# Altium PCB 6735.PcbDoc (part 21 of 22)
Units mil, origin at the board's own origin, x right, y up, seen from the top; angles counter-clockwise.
Board outline 2641.73 x 5165.35 mil, 6 copper layers (Top, Inner Layer 2, Inner Layer 3, Inner Layer 4, Inner Layer 5, Bottom), stack 35.7 mil thick; 1011 components, 790 nets, 4118 pads, 9325 vias.
Unrouted connection lines stored in the file: 4610.
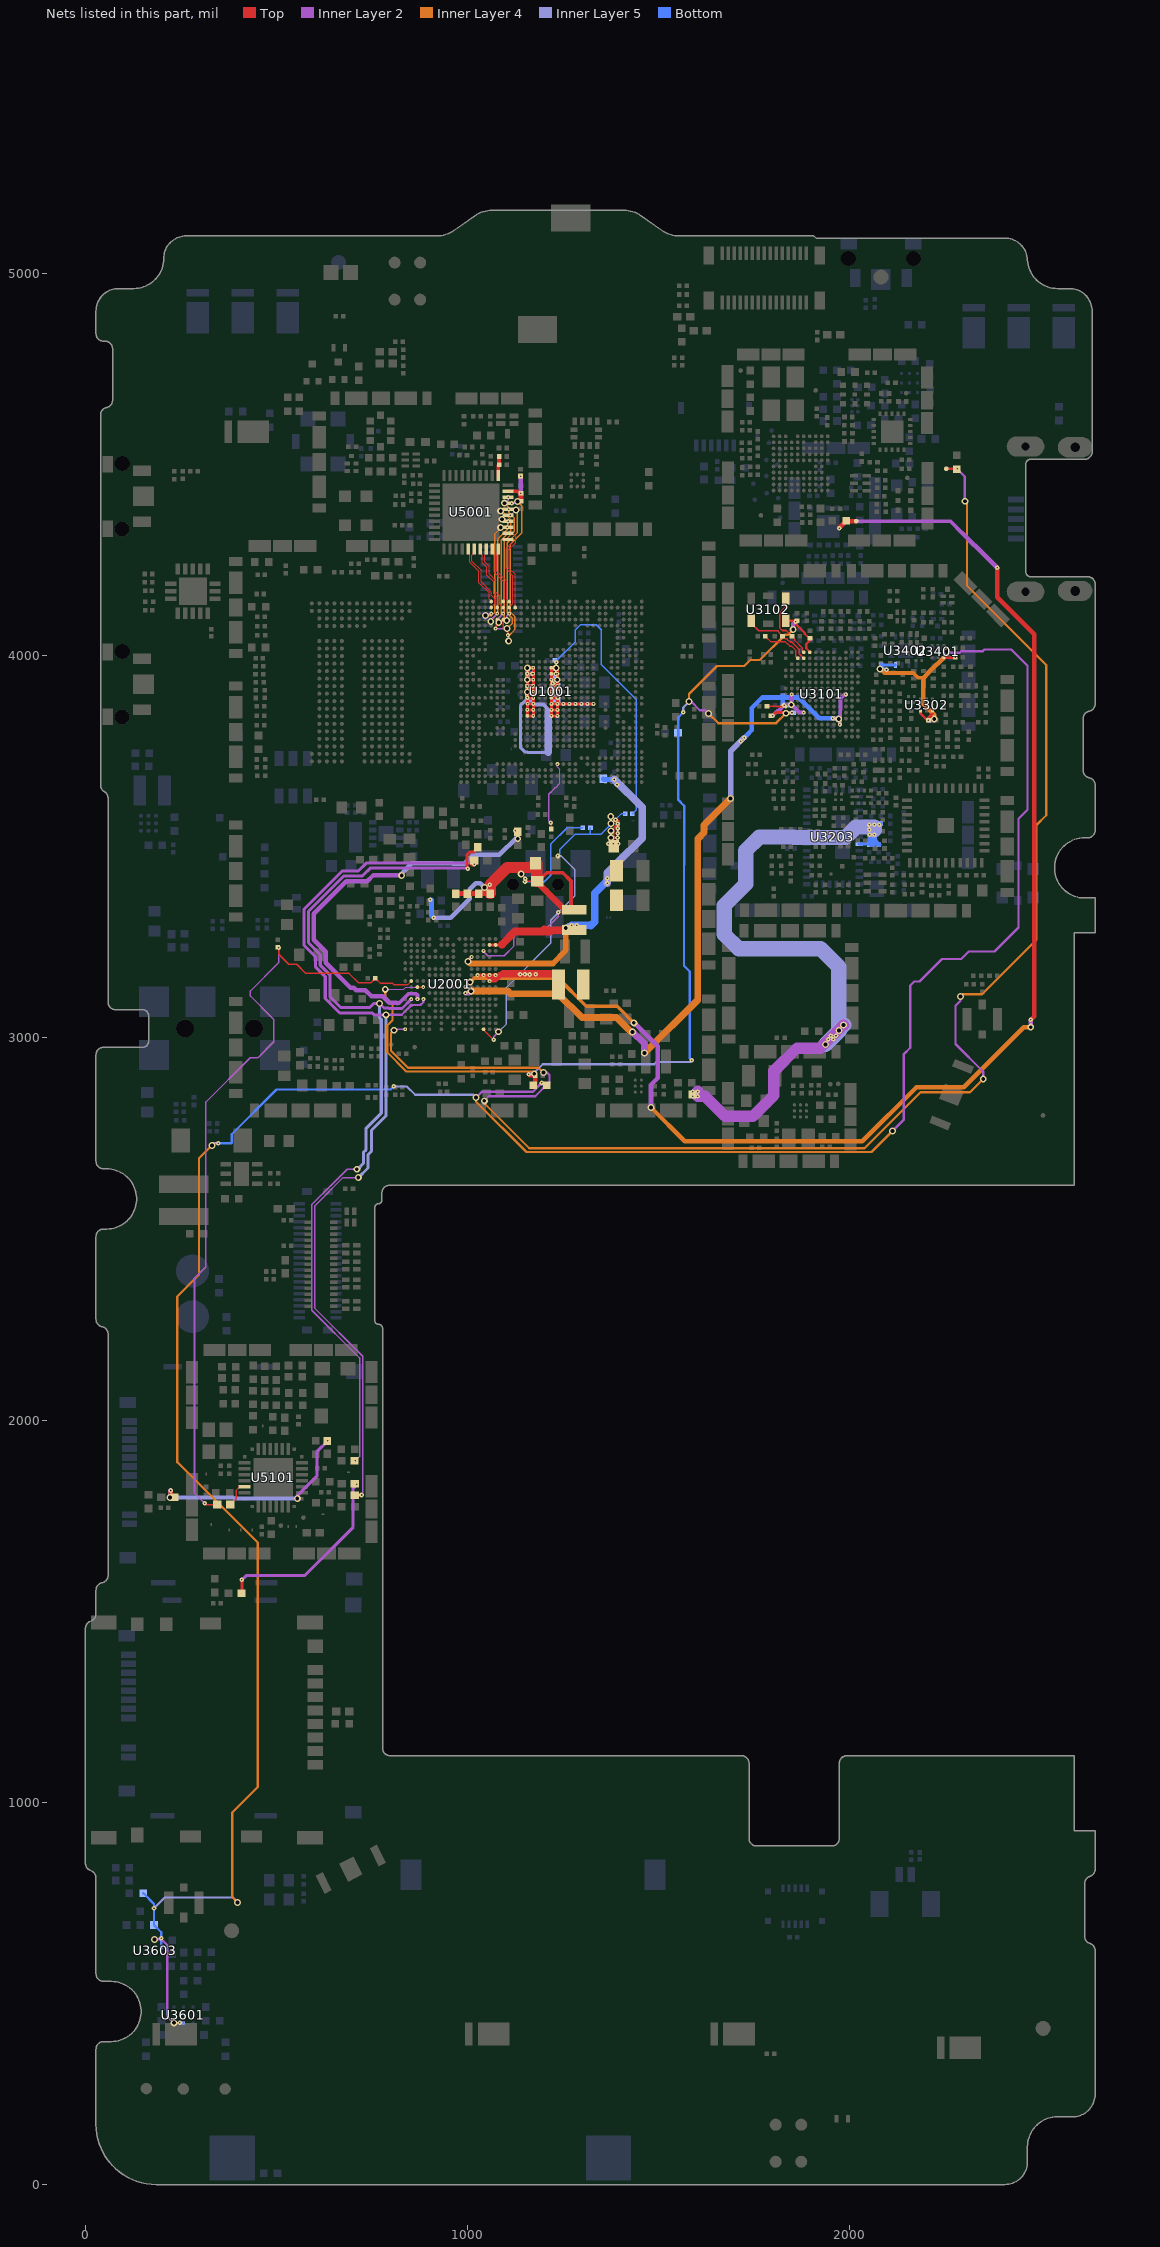
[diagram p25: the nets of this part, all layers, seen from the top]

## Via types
v1: diameter 12, hole 4, Top to Inner Layer 2, 3329 vias
v2: diameter 12, hole 4, Inner Layer 5 to Bottom, 3071 vias
v3: diameter 18, hole 10, Inner Layer 2 to Inner Layer 5, 1928 vias
v4: diameter 10, hole 4, Top to Inner Layer 2, 525 vias
v5: diameter 20, hole 12, Top to Bottom, 472 vias

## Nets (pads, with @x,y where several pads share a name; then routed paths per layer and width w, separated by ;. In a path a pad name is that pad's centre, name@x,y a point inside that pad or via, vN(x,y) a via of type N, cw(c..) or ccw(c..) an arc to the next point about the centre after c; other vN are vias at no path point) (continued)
VPA_VCC2: C3205.1 C3233.1 C3242.1 C3243.1 R3234.1 U3203.28 U3203.30 | length 2323.3
  Top w4: v1(1589.27,2859.22) 1589.38,2859.11 1586.84,2856.56 1587.31,2856.09 R3234.1@1587.31,2852.09 ; v1(1602.31,2847.09) 1594.85,2848.41 1594.42,2847.98 1590.31,2852.09 R3234.1@1587.31,2852.09 ; v1(1602.31,2859.09) 1602.39,2859.81 1595.7,2860.47 1591.86,2856.63 R3234.1@1587.31,2852.09 ; v1(1950.15,3006.09) 1949.32,3005.25 1957.71,2996.86 v1(1956.88,2996.02)
  Inner Layer 2 w4: v1(1963.65,3006.09) v3@1963.65,3014.28
  Inner Layer 2 w30: v1(1602.31,2847.09) 1621.13,2847.09 1673.66,2794.56 1745.99,2794.56 1800.95,2849.52 1800.95,2912.49 1861.76,2973.3 1922.67,2973.3 1963.65,3014.28 1982.96,3033.59 v3(1983.65,3033.59) ; v1(1602.31,2859.09) v1@1602.31,2860.45
  Inner Layer 5 w12: 2063.65,3551.59 v2@2063.65,3557.34 ; v2@2050.59,3557.09 2051.09,3557.09 2051.09,3551.59 v2@2051.09,3545.03 ; v2@2050.59,3557.09 v2(2050.52,3557.09) 2050.52,3557.34 v2@2063.4,3557.34 ; v2@2050.59,3557.09 2050.59,3551.59 2050.59,3544.59 v2(2050.65,3544.59) ; v2(2050.65,3544.59) v2(2050.65,3544.59) ; v2(2050.65,3544.59) v2(2050.65,3544.59) ; v2(2050.65,3544.59) v2(2050.65,3544.59) ; v2(2050.65,3544.59) v2@2051.09,3544.23 ; v2(2050.65,3544.59) v2@2051.09,3544.59 ; v2(2050.65,3544.59) v2@2051.09,3545.03 ; v2@2051.09,3544.23 2051.09,3531.59 v2(2051.65,3531.59) 2051.65,3531.39 v2@2063.93,3531.39 ; v2@2051.09,3544.23 v2@2051.09,3544.59 ; v2@2051.09,3544.23 v2@2063.93,3531.39 ; v2@2051.09,3544.59 v2@2051.09,3545.03 ; v2@2051.09,3544.59 2063.65,3544.59 ; v2@2051.09,3545.03 2057.65,3551.59 v2@2063.4,3557.34 ; v2@2063.4,3557.34 v2@2063.65,3557.34 ; v2@2063.4,3557.34 v2(2063.65,3557.59) v2@2063.65,3557.51 ; 2063.65,3544.59 2063.74,3544.51 2063.82,3544.59 ; 2063.65,3544.59 2063.82,3544.59 ; v2@2063.65,3557.34 v2@2063.65,3557.51 ; v2@2063.65,3557.51 v2@2076.74,3557.51 ; 2063.82,3544.59 2063.93,3544.59 v2@2063.93,3531.39 ; 2063.82,3544.59 v2@2076.74,3557.51 ; v2@2063.93,3531.39 2063.93,3531.18 v2@2064.13,3531.18 ; v2@2063.93,3531.39 v2@2064.13,3531.18 ; v2@2063.93,3531.39 2064.21,3531.39 v2(2064.21,3531.18) ; v2@2064.13,3531.18 v2(2064.21,3531.18) v2(2064.21,3531.18) ; v2@2064.13,3531.18 v2(2064.21,3531.18) ; v2(2064.21,3531.18) 2076.82,3543.79 v2(2076.82,3557.43) ; v2@2076.74,3557.51 2076.82,3557.51 v2(2076.82,3557.43) ; v2@2076.74,3557.51 v2(2076.82,3557.43)
  Inner Layer 5 w30: v3(1971.15,3019.09) v3@1971.9,3018.34
  Inner Layer 5 w40: v3(1936.15,2982.59) v3@1971.9,3018.34 ; v3(1971.15,3019.09) v3@1971.15,3021.09 ; v3(1983.65,3033.59) v3@1971.15,3021.09 ; 2063.65,3544.59 2063.65,3551.59 2057.65,3551.59 2051.09,3551.59 2050.59,3551.59 2015.48,3551.59 1988.48,3524.59 1853.96,3524.59 1852.96,3525.59 1763.15,3525.59 1727.56,3490 1727.56,3402.73 1671.31,3346.48 1671.31,3271.15 1708.97,3233.5 1923.13,3233.5 1971.15,3185.48 v3@1971.15,3021.09
  Bottom w4: C3205.1@2050.65,3505.59 2051.65,3505.59 2053.94,3505.59 2061.65,3505.59 C3242.1@2075.65,3505.59 ; C3243.1@2055.65,3560.59 2055.65,3558.66 2055.65,3557.59 v2(2063.65,3557.59)
  Bottom w8: U3203.30@2024.55,3506.89 2050.65,3506.89 2051.28,3506.07 C3205.1@2051.65,3505.59 ; U3203.28@2024.55,3544.29 2047.72,3544.29 2049.34,3545.91 2050.52,3547.09 v2(2050.52,3557.09)
  Bottom w12: v2(2050.65,3544.59) v2@2051.09,3545.03 ; C3205.1@2053.94,3505.59 2051.65,3507.87 2051.65,3517.59 ; C3243.1@2055.65,3558.66 2050.52,3558.66 v2(2050.52,3557.09) C3243.1@2051.09,3557.09 ; 2061.65,3505.59 2064.65,3508.59 2064.65,3516.59 ; v2(2063.65,3557.59) 2063.65,3560.59 C3233.1@2080.65,3560.59 ; C3242.1@2076.65,3505.59 C3242.1@2075.65,3505.59 2064.65,3516.59 ; v2(2076.82,3557.43) 2076.17,3558.08 2064.65,3546.56 2064.65,3531.18 2064.65,3516.59 ; v2@2051.09,3545.03 2051.09,3531.59 v2(2051.65,3531.59) ; v2@2051.09,3545.03 C3243.1@2051.09,3557.09 ; v2@2051.09,3545.03 2051.15,3545.09 2060.65,3535.59 2060.65,3547.59 2051.15,3557.09 C3243.1@2051.09,3557.09 ; 2051.65,3517.59 2053.65,3517.59 2057.65,3513.59 2061.65,3513.59 2064.65,3516.59 ; 2051.65,3517.59 v2@2051.65,3529.59 ; v2@2051.65,3529.59 v2(2051.65,3531.59) ; v2@2051.65,3529.59 2050.65,3530.59 v2(2051.65,3531.59) ; v2@2051.65,3529.59 2064.65,3516.59
  other v1: 1589.31,2847.09 1943.15,2996.09
VPROC_PMIC_FB: R1036.1 SH1001.2 | length 551.6
  Bottom w4: SH1001.2@1328.31,4081.09 1336.31,4081.09 1349.31,4068.09 1349.31,3977.28 1441.31,3885.28 1441.31,3596.09 1431.31,3586.09 R1036.1@1430.31,3586.09
VPROC_PMIC_FB_6328: R1036.2 R2034.1 U2001.C16 | length 878.5
  Top w4: v1(1067.95,2994.83) 1054.12,3008.66 1053.63,3008.66 1040.57,3021.72 U2001.C16@1041.57,3022.72 ; U2001.C16@1041.57,3022.72 1041.67,3022.83 U2001.C16@1041.57,3022.72
  Inner Layer 2 w4: v1(1067.95,2994.83) 1067.95,3003.2 v3(1080.98,3016.23)
  Inner Layer 5 w4: v3(1080.98,3016.23) 1101.31,3036.56 1101.31,3132.09 1217.31,3248.09 1217.31,3308.09 1280.31,3371.09 1280.31,3440.4 1244.63,3476.09 1236.38,3476.09 v2(1236.3,3476.01)
  Bottom w4: v2(1236.3,3476.01) 1241.31,3481.02 1241.31,3493.47 1280.93,3533.09 1321.31,3533.09 ; R2034.1@1321.31,3550.09 1321.31,3533.09 ; R1036.2@1412.31,3586.09 1401.48,3586.09 1348.48,3533.09 1321.31,3533.09
VPROC_PMU: C10036.1 C10038.1 C10040.1 C10046.1 C10047.1 C10052.1 C10053.1 C10059.1 C10060.1 C10062.1 C10064.1 L2001.2 SH1001.1 U1001.AA14 U1001.AB14 U1001.AC14 U1001.M12 U1001.M13 U1001.M15 U1001.M16 U1001.M17 U1001.M18 U1001.M19 U1001.M20 U1001.N12 U1001.N13 U1001.N14 U1001.N15 U1001.N16 U1001.N17 U1001.N18 U1001.N19 U1001.N20 U1001.T12 U1001.T13 U1001.T14 U1001.T15 U1001.T16 U1001.T17 U1001.T18 U1001.T19 U1001.T20 U1001.U12 U1001.U13 U1001.U14 U1001.U15 U1001.U16 U1001.U17 U1001.U18 U1001.U19 U1001.U20 U1001.V14 U1001.W14 U1001.Y14 | length 2209.6
  Top w4: U1001.M16@1155.96,3905.49 v4(1155.96,3889.74) ; v4(1171.71,3889.74) v4(1155.96,3889.74) ; v1(1368.29,3507.98) 1374.89,3502.98 1376.9,3505.63 1377.21,3506.04 1378.85,3504.8 C10040.1@1381.9,3502.49 ; v1(1392.42,3560.25) 1392.2,3560.02 1382.36,3550.19 C10040.1@1382.36,3507.43 ; v1(1394.4,3507.85) 1390.08,3505.61 1389.31,3507.09 1387.96,3507.09 C10040.1@1382.36,3501.49 ; v4(1155.96,3889.74) 1155.96,3882.48 U1001.M15@1155.96,3889.74 ; C10040.1@1381.9,3502.49 1382.01,3501.45 1382.52,3496.58 1383.31,3496.58 1383.31,3500.54 C10040.1@1382.36,3501.49 ; C10040.1@1381.9,3502.49 v1(1381.31,3508.05) C10040.1@1382.36,3507.43 ; C10040.1@1381.9,3502.49 C10040.1@1382.36,3502.14 ; C10040.1@1382.36,3501.49 C10040.1@1382.36,3502.14 ; C10040.1@1382.36,3501.49 C10040.1@1382.36,3507.43 ; C10040.1@1382.36,3502.14 C10040.1@1382.36,3507.43
  Top w8: 1155.96,3882.48 v4@1155.96,3875.49 ; v4(1171.71,3858.25) v4(1155.96,3858.25) ; v4(1171.71,3873.99) v4@1157.45,3873.99 ; U1001.N15@1171.71,3889.74 1155.96,3889.74 U1001.M16@1155.96,3905.49 ; v4(1171.71,3905.49) U1001.M16@1155.96,3905.49 ; v4(1171.71,3921.24) v4(1155.96,3921.24) ; v4(1171.71,3936.99) U1001.M18@1155.96,3936.99 ; v4(1171.71,3952.73) v4(1155.96,3952.73) ; v4(1329.19,3873.99) v4(1266.2,3873.99) v4(1234.7,3873.99) ; v4(1155.96,3858.25) U1001.M12@1155.96,3842.5 v4(1171.71,3842.5) v4(1171.71,3968.48) ; v4(1155.96,3858.25) v4@1155.96,3875.49 ; v4@1155.96,3875.49 v4(1156.95,3874.49) ; v4@1155.96,3875.49 v4@1156.95,3874.49 ; U1001.M16@1155.96,3905.49 v4(1155.96,3921.24) ; v4(1155.96,3921.24) U1001.M18@1155.96,3936.99 ; U1001.M18@1155.96,3936.99 v4(1155.96,3952.73) ; U1001.M18@1155.96,3936.99 v4(1155.96,3952.73) ; U1001.M18@1155.96,3936.99 v4(1155.96,3952.73) ; v4(1155.96,3952.73) U1001.M20@1155.96,3968.48 ; v4(1155.96,3952.73) U1001.M20@1155.96,3968.48 ; v4(1155.96,3952.73) U1001.M20@1155.96,3968.48 ; U1001.M20@1155.96,3968.48 v4(1171.71,3968.48) ; U1001.M20@1155.96,3968.48 v4(1171.71,3968.48) ; v4(1156.95,3874.49) v4@1157.45,3873.99 ; v4@1156.95,3874.49 v4@1157.45,3873.99 ; v4(1218.95,3858.25) v4(1234.7,3858.25) ; v4(1218.95,3858.25) v4(1218.95,3873.99) ; v4(1218.95,3858.25) v4(1218.95,3842.5) v4(1234.7,3842.5) v4(1234.7,3858.25) ; v4(1218.95,3873.99) U1001.T15@1218.95,3889.74 ; v4(1218.95,3873.99) v4(1234.7,3873.99) ; U1001.T15@1218.95,3889.74 U1001.U15@1234.7,3889.74 ; U1001.T15@1218.95,3889.74 v4(1218.95,3905.49) ; v4(1218.95,3905.49) U1001.U16@1234.7,3905.49 ; v4(1218.95,3905.49) U1001.T17@1218.95,3921.24 ; U1001.T17@1218.95,3921.24 v4(1234.7,3921.24) ; U1001.T17@1218.95,3921.24 v4(1218.95,3936.99) ; v4(1218.95,3936.99) U1001.U18@1234.7,3936.99 ; v4(1218.95,3936.99) U1001.T19@1218.95,3952.73 ; v4(1218.95,3936.99) U1001.U18@1234.7,3936.99 ; U1001.T19@1218.95,3952.73 v4(1234.7,3952.73) ; U1001.T19@1218.95,3952.73 U1001.T20@1218.95,3968.48 ; U1001.T20@1218.95,3968.48 U1001.U20@1234.7,3968.48 ; U1001.T20@1218.95,3968.48 U1001.U20@1234.7,3968.48 ; v4(1234.7,3858.25) v4(1234.7,3873.99) ; v4(1234.7,3873.99) U1001.U15@1234.7,3889.74 ; v4(1234.7,3889.74) U1001.U16@1234.7,3905.49 ; U1001.U16@1234.7,3905.49 v4(1234.7,3921.24) ; v4(1234.7,3921.24) U1001.U18@1234.7,3936.99 ; v4(1234.7,3921.24) U1001.U18@1234.7,3936.99 ; U1001.U18@1234.7,3936.99 v4(1234.7,3952.73) ; U1001.U18@1234.7,3936.99 v4(1234.7,3952.73) ; v4(1234.7,3952.73) U1001.U20@1234.7,3968.48 ; v4(1234.7,3952.73) U1001.U20@1234.7,3968.48
  Top w12: v1(1386.78,3571.02) 1392.2,3565.6 1392.2,3560.02 v1(1392.2,3547.96)
  Inner Layer 2 w8: v4(1155.96,3889.74) v3(1156.08,3905.1) ; v4(1171.71,3873.99) v4(1171.71,3905.49) 1156.08,3905.49 v3(1156.08,3968.1) 1156.45,3968.48 v4(1171.71,3968.48) ; v4(1218.95,3905.49) v3@1234.08,3905.49 ; v4(1218.95,3936.99) v3@1234.08,3936.98 ; v3(1231.58,3968.11) 1234.08,3965.61 v3@1234.08,3936.98 ; v3(1234.39,3937.1) v3@1234.08,3936.98 ; v4(1329.19,3873.99) v4(1313.44,3873.99) v4(1234.7,3873.99) ; v4@1234.08,3873.99 v4(1234.7,3873.99) ; v4@1234.08,3873.99 v4(1234.7,3873.99) ; v4@1234.08,3873.99 v3(1234.08,3905.1) v3@1234.08,3905.49 ; v3@1234.08,3905.49 1234.08,3921.24 v3@1234.08,3936.98
  Inner Layer 5 w4: v3@1156.08,3966.62 v3(1156.08,3968.1)
  Inner Layer 5 w8: v2(1155.92,3889.98) 1157.45,3888.45 1137.95,3868.96 1137.95,3760.49 1150.95,3747.49 1156.64,3747.49 1157.03,3747.1 1210.56,3747.1 1210.95,3747.49
  Inner Layer 5 w10: v2(1155.95,3952.49) 1156.07,3966.6 v3(1156.08,3968.1) ; v2@1157.45,3888.45 1173.41,3872.49 1198.51,3872.49 1210.95,3860.04 1210.95,3853.44
  Inner Layer 5 w20: 1210.95,3747.49 1210.95,3853.44
  Bottom w4: v2(1231.38,3983.3) C10053.1@1228.31,3988.09 1233.31,3988.09 1281.31,4036.09 1281.31,4066.9 1295.5,4081.09 SH1001.1@1324.31,4081.09 ; C10060.1@1227.4,3951.6 v2(1230.31,3952.09) 1228.31,3951.09 C10060.1@1228.31,3946.09 C10060.1@1227.4,3951.6
  Bottom w12: v2(1155.95,3920.49) v2(1169.95,3920.49) ; C10064.1@1155.95,3946.49 v2(1155.95,3952.49) v2(1168.95,3952.49)
  other v1: 1392.04,3523.31 1392.29,3535.67
  other v2: 1236.45,3889.86 1221.75,3896.01 1223.09,3915.71 1222.31,3928.09
  other v3: 1375.31,3523.57 1375.31,3541.82 1375.31,3560.86 1374.19,3579.32 1156.02,3937.04
  other v4: 1250.45,3873.99 1281.94,3873.99 1297.69,3873.99
VPROC_SW: L2001.1 U2001.A7 U2001.B7 U2001.B8 U2001.C7 U2001.D7 | length 518
  Top w4: v4(1025.82,3164.45) v4(1041.57,3164.45)
  Top w8: v4(1025.82,3164.45) v4(1041.57,3164.45) 1048.15,3164.45 ; 1048.15,3164.45 v4(1057.32,3164.45) ; 1048.15,3164.45 1057.31,3155.29 ; v4(1057.32,3148.7) 1060.61,3152 1057.54,3155.06 ; v4(1057.32,3148.7) 1057.31,3154.83 ; v4(1057.32,3148.7) 1062.82,3148.7 ; v4(1057.32,3148.7) v4(1073.06,3164.45) ; v4(1057.32,3148.7) 1057.31,3154.83 ; v4(1057.32,3148.7) 1062.82,3148.7 ; v4(1057.32,3148.7) v4(1073.06,3164.45) ; 1057.31,3154.83 1057.31,3155.29 ; 1057.31,3154.83 1057.31,3155.29 ; 1057.31,3154.83 1057.54,3155.06 ; 1057.31,3155.29 v4(1057.32,3164.45) ; 1057.31,3155.29 v4(1057.32,3164.45) ; 1057.31,3155.29 1057.54,3155.06 ; v4(1057.32,3164.45) v4(1073.06,3164.45) ; 1057.54,3155.06 1066.93,3164.45 v4(1073.06,3164.45) ; 1062.82,3148.7 1074.04,3148.7 1093.16,3167.83 1081.95,3167.83 U2001.A7@1075.82,3161.7 ; 1062.82,3148.7 U2001.A7@1075.82,3161.7 ; v4(1073.06,3164.45) U2001.A7@1075.82,3161.7 ; v4(1073.06,3164.45) 1077.95,3164.45 v4(1073.06,3164.45) ; v4(1073.06,3164.45) U2001.A7@1075.82,3161.7
  Top w12: L2001.1@1232.47,3144.83 L2001.1@1237.47,3139.83 L2001.1@1232.47,3144.83
  Top w20: 1093.16,3167.83 1149.95,3167.83 1232.47,3167.83 1232.47,3144.83 1232.47,3142.33 L2001.1@1237.47,3139.83
  Inner Layer 2 w4: v4(1025.82,3164.45) v4(1041.57,3164.45) v4(1057.32,3164.45) v4(1073.06,3164.45)
  other v1: 1149.95,3166.47 1162.95,3165.83 1136.95,3166.83 1177.95,3166.83
VRF18_0_PMU: C3101.1 C3104.1 C3112.1 C3116.1 U2001.F10 U3101.C8 U3101.D13 U3101.K11 U3101.M8 U3101.N11 | length 2326.1
  Top w4: C3101.1@1793.15,3843.09 C3101.1@1797.37,3843.09 ; 1802.69,3847.63 C3101.1@1798.81,3843.75 ; C3101.1@1797.37,3843.09 v1(1798.15,3843.09) C3101.1@1798.81,3843.75 ; C3101.1@1797.37,3843.09 1798.81,3841.65 C3101.1@1798.81,3843.75
  Top w8: 1802.69,3847.63 1806.41,3851.35 U3101.N11@1832.16,3851.35
  Inner Layer 2 w10: v1(1798.15,3843.09) 1810.61,3855.55 1813.15,3855.55 1829.19,3871.58 v3(1846.51,3871.58) 1847.19,3872.25 v3@1847.65,3872.25 ; v4(1847.91,3898.59) 1847.65,3898.59 v3@1847.65,3872.25 ; v4(1879.41,3851.35) 1868.56,3851.35 v3@1847.65,3872.25 ; v4(1973.9,3819.85) 1973.9,3831.35 v3(1970.65,3834.59) 1974.65,3838.59 1974.65,3858.52 1975.4,3859.27 1975.4,3888.4 1985.59,3898.59 v4(1989.64,3898.59)
  Inner Layer 2 w12: v4(994.32,3117.21) 1003.61,3117.21 v3(1008.7,3122.3)
  Inner Layer 2 w18: v3(1431.58,3015.54) 1431.78,3015.74 1462.69,2984.83 v3(1462.69,2960.38)
  Inner Layer 4 w18: v3(1008.7,3122.3) 1105.47,3122.3 1112.35,3115.42 1236.87,3115.42 1299.33,3052.96 1390.06,3052.96 1427.48,3015.54 v3(1431.58,3015.54) ; v3(1462.69,2960.38) 1601.97,3099.66 1601.97,3520.64 1618.63,3537.3 1618.63,3556.57 1688.08,3626.01 v3(1688.08,3626.71)
  Inner Layer 5 w4: v2(1714.31,3776.65) 1720.71,3776.65 1724.56,3780.5 1724.56,3784.18 1723.18,3785.56 v2(1714.31,3776.65)
  Inner Layer 5 w10: v2(1955.65,3836.59) 1955.65,3835.59 1970.65,3835.59 v3(1970.65,3834.59)
  Inner Layer 5 w12: v2(1827.67,3870.59) 1827.67,3871.09 1846.51,3871.09 v3(1846.51,3871.58)
  Inner Layer 5 w15: v3(1688.08,3626.71) 1688.08,3750.51 v2(1723.15,3785.59)
  Bottom w4: C3112.1@1824.65,3870.59 v2(1827.67,3870.59) ; C3116.1@1824.65,3895.59 1865.99,3895.59 1920.2,3841.38 1921.86,3841.38 1926.65,3836.59
  Bottom w12: v2(1714.31,3776.65) 1729.81,3792.15 ; v2(1723.15,3785.59) 1729.71,3792.15 1729.81,3792.15 ; C3112.1@1824.65,3870.59 C3116.1@1824.65,3890.59 ; C3116.1@1824.65,3895.59 C3116.1@1824.65,3890.59 ; v2(1955.65,3836.59) 1926.65,3836.59 1919.39,3836.59 1865.39,3890.59 C3116.1@1824.65,3890.59 ; 1729.81,3792.15 1743.15,3805.49 1743.15,3863.09 1770.65,3890.59 C3116.1@1824.65,3890.59
VRF18_1_PMU: R3713.1 TP3719.1 U2001.F9 | length 3710.9
  Top w3: v1(1972.46,4333.41) 1972,4333.87 1972.46,4334.33 R3713.1@1990.3,4352.17 ; R3713.1@1990.3,4353.09 R3713.1@1990.3,4352.63 ; R3713.1@1990.3,4352.17 1990.76,4352.63 R3713.1@1990.3,4352.63 ; R3713.1@1990.3,4352.17 R3713.1@1990.3,4352.63
  Top w12: v1(1972.46,4333.41) 1972.46,4334.33 1972.46,4335.25 R3713.1@1990.3,4353.09 ; R3713.1@1990.3,4352.17 1990.3,4352.09 TP3719.1@2016.31,4352.09 ; v1(2385.31,4230.09) 2385.31,4153.16 2482.31,4056.16 2482.31,3056.09 v1(2473.31,3047.09)
  Inner Layer 2 w8: v4(994.32,3132.96) 994.31,3134.09 1004.31,3144.09 1004.31,3145.83 v3(1006.4,3145.83)
  Inner Layer 2 w10: v1(1972.46,4333.41) 1972.17,4333.7 1990.3,4351.83 2262.96,4351.83 2294.96,4319.83
  Inner Layer 2 w12: v3(1434.68,3039.45) v3@1435.34,3040.12 ; v3@1435.35,3040.11 1497.31,2978.14 1497.31,2895.19 1479.57,2877.45 v3(1479.57,2817.83) ; 2294.96,4319.83 2325.71,4289.09 2326.31,4289.09 v1(2385.31,4230.09) ; v3(2473.31,3028.09) 2474.31,3029.09 2473.31,3030.09 v1(2473.31,3047.09)
  Inner Layer 4 w10: v3(1006.4,3145.83) 1017.4,3156.83 1236.37,3156.83 1310.37,3082.83 1391.29,3082.83 v3(1434.68,3039.45)
  Inner Layer 4 w12: v3(1479.57,2817.83) 1568.1,2729.3 2032.55,2729.3 2174.18,2870.93 2297.88,2870.93 2455.04,3028.09 v3(2473.31,3028.09)
VRT: R3105.1 U3101.N10 | length 49.4
  Top w4: R3105.1@1783.15,3868.09 1807.7,3868.09 1808.7,3867.09 U3101.N10@1832.16,3867.09
VRTC: C2032.1 R2026.1 SH5110.1 U2001.R8 | length 2067.1
  Top w4: v1(312.31,1782.09) 315.31,1779.09 SH5110.1@344.31,1779.09 ; R2026.1@503.31,3237.09 503.31,3236.31 v1(505.6,3236.31) 505.6,3218.99 532.09,3192.5 552.56,3192.5 576.23,3168.83 689.6,3168.83 714.34,3144.09 746.8,3144.09 750.61,3147.9 750.61,3148.38 C2032.1@758.31,3156.09 771.9,3142.5 804.15,3142.5 807.56,3139.09 827.87,3139.09 828.18,3138.78 842.67,3138.78 U2001.R8@852.59,3148.7
  Inner Layer 2 w4: v1(312.31,1782.09) 285.31,1809.09 285.31,2371.18 315.31,2401.18 315.31,2832.35 431.3,2948.34 451.19,2948.34 492.75,2989.9 492.75,3048.51 431.59,3109.67 431.59,3122.95 505.6,3196.96 v1(505.6,3236.31)
VRTC_NFC: SH5110.2 U5101.30 | length 71.2
  Top w4: SH5110.2@378.31,1779.09 379.31,1779.09 394.03,1793.81 394.03,1815.83 404.38,1826.17 416.4,1826.17 U5101.30@416.4,1825.47
VSIM1_NFC: SH5101.1 SH6501.1 | length 562.6
  Top w4: SH5101.1@632.95,1945.49 632.95,1946.49 v1(633.95,1945.49)
  Top w12: v1(223.44,1815.83) 223.44,1807.34 232.95,1797.83 SH6501.1@231.95,1797.83
  Inner Layer 2 w8: v3(554.31,1795.09) 554.31,1801.84 605.31,1852.84 605.31,1916.85 v1(633.95,1945.49)
  Inner Layer 2 w12: v3(221.51,1797.83) 222.48,1797.83 222.48,1815.83 v1(223.44,1815.83)
  Inner Layer 5 w10: v3(221.51,1797.83) 386.57,1797.83 389.31,1795.09 v3(554.31,1795.09)
VSIM1_PMU: R1022.2 SH5102.1 U2001.R11 | length 2378.5
  Top w4: SH5102.1@703.95,1893.49 v1(705.95,1893.49)
  Top w8: v1(1000.46,3442.63) 998.31,3444.78 998.31,3479.09 1005.31,3486.09 1014.55,3486.09 R1022.2@1025.95,3497.49
  Inner Layer 2 w4: v1(705.95,1893.49) 717.14,1904.68 717.14,2162.67 592.31,2287.5 592.31,2563.99 684.72,2656.4 v3(709.96,2656.4)
  Inner Layer 2 w8: v4(852.59,3101.46) 828.22,3077.09 794.71,3077.09 793.71,3078.09 781.31,3078.09 v3(769.31,3090.09) 754.31,3090.09 743.31,3079.09 668.51,3079.09 639.31,3108.29 639.31,3165.37 614.31,3190.37 614.31,3218.32 583.31,3249.32 583.31,3331.09 676.31,3424.09 725.04,3424.09 746.04,3445.09 998.01,3445.09 v1(1000.46,3442.63)
  Inner Layer 5 w8: v3(709.96,2656.4) 711.05,2655.31 727.06,2671.32 727.06,2700.08 734.56,2707.58 734.56,2763.62 773.95,2803.01 773.95,3048.5 769.31,3053.14 v3(769.31,3090.09)
VSIM2_NFC: SH5104.1 SH6502.1 | length 506.2
  Top w4: SH5104.1@704.95,1833.49 708.91,1833.49 v1(710.31,1832.09)
  Top w8: SH6502.1@408.31,1547.09 409.31,1547.09 409.31,1567.09 v1(409.31,1582.09)
  Inner Layer 2 w8: v1(409.31,1582.09) 420.33,1593.11 573.33,1593.11 700.33,1720.11 700.33,1822.11 v1(710.31,1832.09)
VSIM2_PMU: R1023.2 SH5105.1 U2001.N11 | length 2499.4
  Top w8: SH5105.1@704.95,1803.49 704.95,1804.09 v1(722.31,1804.09)
  Top w12: R1023.2@1017.31,3464.09 1016.31,3464.09 1016.31,3461.09 1019.31,3461.09 1012.31,3454.09 1017.32,3454.1 v1(1017.46,3454.1)
  Inner Layer 2 w4: v3(713.92,2634.44) 674.07,2634.44 600.31,2560.68 600.31,2292.25 725.19,2167.37 725.19,1806.97 v1(722.31,1804.09)
  Inner Layer 2 w6: v3(786.4,3060.39) 827.67,3060.39 853.38,3086.09 876.71,3086.09 884.08,3093.46 v4(884.09,3101.46)
  Inner Layer 2 w8: v3(786.4,3060.39) 755.3,3060.39 750.59,3065.09 665.54,3065.09 627.31,3103.32 627.31,3160.35 601.31,3186.35 601.31,3213.14 571.31,3243.14 571.31,3336.06 672.34,3437.09 714.34,3437.09 734.34,3457.09 1014.47,3457.09 v1(1017.46,3454.1)
  Inner Layer 5 w8: v3(713.92,2634.44) 739.31,2659.83 739.31,2694.65 748.31,2703.65 748.31,2758.09 786.4,2796.17 v3(786.4,3060.39)
VSRAM_PMU: C2046.1 R1027.2 U2001.E4 | length 973.6
  Inner Layer 2 w8: v3(1001.14,3199.58) 1003.12,3198.38 1003.12,3204.75 v4(1010.07,3211.7)
  Inner Layer 4 w15: v3(1001.14,3199.58) 1003.12,3198.38 1005.95,3194.83 1222.95,3194.83 1256.65,3228.53 v3(1256.65,3287.58)
  Inner Layer 5 w4: v2(1365.03,3405.2) 1365.11,3405.2 1365.11,3417.59 v2(1365.19,3417.59) 1365.19,3417.94 v2@1365.03,3418.09
  Inner Layer 5 w12: v3(1256.65,3287.58) 1263.16,3294.09 1272.61,3294.09 v2(1272.61,3294.66) 1272.61,3294.76 1285.36,3294.76 v2(1285.36,3294.85)
  Inner Layer 5 w20: v2(1365.03,3405.2) 1365.03,3418.09 1365.03,3431.81 1391.31,3458.09 1391.73,3458.09 1456.31,3522.67 1456.31,3603.09 v2(1383.31,3676.09)
  Bottom w12: R1027.2@1354.31,3678.09 1354.31,3676.09 v2(1383.31,3676.09) 1383.31,3669.55 v2(1390.66,3662.2)
  Bottom w20: v2(1272.61,3294.66) 1286.31,3294.66 1321.74,3294.66 1322.31,3294.09 1332.31,3304.09 1332.31,3378.09 1365.19,3410.97 v2(1365.19,3417.59) ; v2(1285.36,3294.85) v2@1286.3,3294.68
VSYS_PMU: C2039.1 C2040.1 L2008.2 R2034.2 R2039.1 R2040.1 R2041.1 R2046.1 U2001.C3 | length 1706.8
  Top w4: v1(1057.61,3401.1) 1057.69,3401.19 v1@1058.95,3401.19 ; R2040.1@1058.95,3376.83 1058.95,3377.83 1062.57,3377.83 R2040.1@1065.31,3375.09 ; v1(1150.95,3416.83) 1158.1,3409.68 1175.95,3409.68 C2040.1@1182.31,3409.68 1182.31,3425.68 1181.49,3426.5 1180.31,3426.5 ; v1(1237.14,3328.64) 1251.76,3328.64 1258.3,3335.18 L2008.2@1278.92,3335.18 ; L2008.2@1278.92,3335.18 1303.45,3327.99 L2008.2@1301.45,3329.99 ; L2008.2@1278.92,3335.18 L2008.2@1301.45,3329.99 ; L2008.2@1301.45,3329.99 1296.25,3335.18 L2008.2@1278.92,3335.18 L2008.2@1301.45,3329.99
  Top w10: C2040.1@1182.31,3409.68 1184.31,3409.68 1206.72,3432.09 1248.85,3432.09 1270.31,3410.63 1270.31,3343.79 L2008.2@1278.92,3335.18
  Top w12: R2039.1@968.95,3377.83 R2040.1@1058.95,3377.83 ; R2040.1@1058.95,3379.09 R2040.1@1064.31,3379.09
  Top w15: L2008.2@1258.3,3335.18 L2008.2@1278.92,3335.18
  Top w16: C2040.1@1182.31,3409.68 1182.31,3407.03 1203.92,3385.42 1204.31,3385.42 1254.55,3335.18 L2008.2@1278.92,3335.18
  Top w18: L2008.2@1253.07,3335.18 L2008.2@1278.92,3335.18
  Top w30: R2040.1@1058.95,3377.83 1058.95,3379.09 1058.95,3401.19 1103.6,3445.83 1166.46,3445.83 C2039.1@1177.72,3457.09 1180.31,3457.09 1180.31,3426.5 1180.31,3409.68 C2040.1@1182.31,3409.68
  Inner Layer 2 w4: v4(1041.57,3227.44) 1040.61,3226.49 1052.27,3214.83 1095.58,3214.83 1120.95,3240.2 1120.95,3265.85 1135.93,3280.83 1200.17,3280.83 1237.14,3317.81 v1(1237.14,3328.64) ; v3(1139.95,3428.83) 1139.7,3428.58 1151.2,3417.08 v1(1150.95,3416.83)
  Inner Layer 2 w12: v3(1043.67,3393.83) 1050.94,3401.1 v1(1057.61,3401.1)
  Inner Layer 5 w4: v3(1139.95,3428.83) 1149.95,3418.83 v2(1149.95,3408.83)
  Inner Layer 5 w12: v2(910.95,3314.83) 955.55,3314.83 1004.95,3364.23 1004.95,3388.7 1020.69,3404.44 1033.06,3404.44 v3(1043.67,3393.83)
  Bottom w4: v2(1149.95,3408.83) 1200.43,3408.83 1217.31,3425.72 1217.31,3507.09 1260.31,3550.09 R2034.2@1301.31,3550.09
  Bottom w12: v2(902.31,3361.09) 905.31,3361.09 905.31,3320.09 v2(910.95,3314.83)
VSYS_SW: L2008.1 U2001.A2 U2001.B2 | length 268.6
  Top w8: U2001.B2@1057.32,3243.19 U2001.A2@1073.06,3243.19 1089.95,3243.19 1089.95,3243.83
  Top w20: 1089.95,3243.83 1089.95,3244.63 1123.81,3278.49 1215.76,3278.49 1207.19,3282.04 ; L2008.1@1278.92,3282.04 1207.19,3282.04 ; 1207.19,3282.04 1201.12,3284.55 1203.63,3282.04 1207.19,3282.04
VTCXO2: C3312.1 C3407.1 C3435.1 R3380.2 R3625.2 R3626.2 U3302.1 U3302.7 U3401.7 U3402.4 U3601.4 U3601.5 U3603.4 | length 7262.7
  Top w6: v1(1193.49,2882.14) v1@1194.95,2883.49
  Top w8: U3302.7@2184.9,3854.84 2184.9,3848.78 2203.1,3830.59 v1(2205.35,3830.59) C3312.1@2205.65,3830.59 2205.65,3837.84 2216.4,3848.59 U3302.1@2216.4,3854.84 ; U3401.7@2246.4,3994.84 2274.9,3994.84 v1(2275.65,3995.59)
  Top w10: v1(1193.49,2882.14) 1197.3,2882.14 1205.25,2874.19 1207.15,2874.19 R3380.2@1207.15,2876.09
  Inner Layer 2 w6: v3(180.3,641.09) 198.3,642.09 214.31,626.08 214.31,439.08 231.01,422.38 v3(231.72,423.09) ; v3(1021.71,2843.77) 1036.76,2858.83 1170.19,2858.83 v1(1193.49,2882.14) ; v3(2111.72,2756.78) 2141.31,2786.37 2141.31,2957.79 2157.65,2974.13 2157.65,3137.12 2168.21,3147.67 2182.28,3147.67 2241.03,3206.41 2291.1,3206.41 2310.73,3226.04 2378.57,3226.04 2441.28,3288.75 2441.28,3573.27 2464.86,3596.85 2464.86,3973.52 2422.29,4016.09 2351.92,4016.09 2347.3,4011.47 2316.47,4011.47 2316.33,4011.61 2308.94,4011.61 ; v3@2253.18,4010.39 2253.85,4009.95 2256.18,4008.39 2258.65,4007.59 2287.5,4007.59 2291.5,4011.59 2308.92,4011.59
  Inner Layer 2 w8: v3(2254.48,4010.89) 2253.18,4010.89 2253.18,4010.39 2253.18,4002.89 2260.48,3995.59 v1(2275.65,3995.59)
  Inner Layer 2 w12: v1(2205.35,3830.59) 2216.65,3830.59 v3(2220.65,3834.59)
  Inner Layer 4 w6: v3(330.91,2718.88) 297.31,2685.28 297.31,2380.41 240.31,2323.41 240.31,1890.15 450.95,1679.51 450.95,1040.09 384.31,973.45 384.31,752.03 v3(398.2,738.14) ; v3(1021.71,2843.77) 1021.71,2833.2 1153.6,2701.3 2056.24,2701.3 v3(2111.72,2756.78)
  Inner Layer 4 w10: v3(2079.15,3965.09) 2089.76,3954.48 2166.65,3954.48 2167.11,3954.03 2167.11,3953.72 2177.65,3943.17 2177.96,3943.17 2178.68,3942.46 2191.65,3942.46 2191.66,3942.17
  Inner Layer 4 w12: 2191.66,3942.17 2192.98,3942.17 2204.11,3953.3 2204.11,3953.62 2253.18,4002.69 2253.18,4010.89 v3(2254.48,4010.89) ; 2191.65,3942.46 2191.65,3874.59 2220.65,3845.59 v3(2220.65,3834.59)
  Inner Layer 5 w4: v3(231.72,423.09) v2(247.3,423.09)
  Inner Layer 5 w6: v2(179.31,723.09) 207.31,751.09 385.25,751.09 v3(398.2,738.14) ; v3(180.3,641.09) v2(198.3,644.09) ; v3(330.91,2718.88) 330.91,2724.4 v2(347.63,2724.4) ; v2(806.31,2873.09) 840.69,2873.09 862.78,2851 1014.48,2851 v3(1021.71,2843.77)
  Inner Layer 5 w10: v3(2079.15,3965.09) 2079.15,3964.12 2095.81,3964.12 v2(2095.81,3963.15)
  Bottom w6: R3626.2@150.95,762.49 179.3,734.14 v2@179.3,725.09 ; U3603.4@198.06,618.96 198.06,644.09 198.06,644.32 v2(198.3,644.09) 198.3,660.09 R3625.2@179.3,679.09 v2(179.31,723.09) ; U3601.5@231.43,422.32 v2@244.3,422.32 ; v2(247.3,423.09) 243.53,423.09 v2@244.3,422.32 ; U3601.4@256.43,422.32 247.3,422.32 v2@244.3,422.32 ; v2(347.63,2724.4) 381.58,2724.4 382.74,2725.56 382.74,2747.82 500.01,2865.09 798.31,2865.09 v2(806.31,2873.09) ; v2(179.31,723.09) v2@179.31,725.07 ; v2(179.31,723.09) v2@179.3,725.09
  Bottom w8: C3435.1@2081.65,3976.09 2081.79,3976.09 2101.26,3976.09 2101.7,3975.65 U3402.4@2119.24,3975.65
  Bottom w10: C3435.1@2081.79,3976.09 2081.79,3969.46 2088.1,3963.15 v2(2095.81,3963.15)
VTCXO_0_PMU: C3102.1 C3103.1 C3110.1 C3383.1 R1035.2 R3380.1 U2001.P9 U3101.J1 U3101.M11 U3102.6 | length 3022.3
  Top w4: U2001.P9@868.34,3132.96 868.34,3132.89 883.95,3132.89 v4(883.95,3132.83) ; v1(1858.85,4088.51) 1861.54,4091.2 C3110.1@1861.62,4091.28 ; C3110.1@1861.65,4091.09 C3110.1@1861.65,4091.25
  Top w6: U3102.6@1831.93,4091.55 1861.19,4091.55 1861.54,4091.2 C3110.1@1861.65,4091.09 1861.65,4079.78 1882.15,4059.28 1882.15,4057.19 1894.7,4044.64 1894.7,4045.59 C3103.1@1895.65,4045.59 1895.65,4040.71 1885.77,4030.83 1885.77,4019.35 1895.16,4009.96 U3101.J1@1895.16,4008.83
  Top w10: v1(1159.31,2905.09) 1162.65,2901.76 1176.65,2901.76 C3383.1@1176.65,2901.09
  Top w12: R3380.1@1171.15,2876.09 1176.65,2881.59 C3383.1@1176.65,2901.09
  Inner Layer 2 w3: v3(784.31,3127.09) 833.31,3127.09 838.12,3131.9 883.95,3131.9 v4(883.95,3132.83)
  Inner Layer 2 w6: v1(1159.31,2905.09) 1159.31,2905.59 1174.31,2905.59 v3(1174.31,2906.09) ; v3(1578.95,3879.83) 1584.69,3879.83 1606.97,3857.56 1621.39,3857.56 v3(1629.87,3849.07)
  Inner Layer 2 w10: v3(1833,3849.4) 1832.79,3849.4 1832.79,3850.59 1832.65,3850.59 1832.65,3850.97 1847.91,3850.97 v4(1847.91,3851.35)
  Inner Layer 2 w12: v3(1851.65,4068.59) 1851.65,4083.59 1857.71,4089.65 v1(1858.85,4088.51)
  Inner Layer 4 w6: v3(784.31,3127.09) 784.31,3106.82 803.31,3087.82 803.31,3046.37 789.31,3032.37 789.31,2962.38 839.6,2912.09 1168.31,2912.09 v3(1174.31,2906.09) ; v3(1578.95,3879.83) 1578.95,3899.63 1652.28,3972.96 1723.66,3972.96 1739.29,3988.59 1764.33,3988.59 1830.18,4054.44 1837.5,4054.44 v3(1851.65,4068.59) ; v3(1629.87,3849.07) 1655.35,3823.59 1806.98,3823.59 1832.79,3849.4 v3(1833,3849.4)
  Inner Layer 5 w6: v3(1174.31,2906.09) 1172.83,2907.58 1196.34,2931.09 1488.31,2931.09 1494.31,2937.09 1582.24,2937.09 v2(1586.28,2941.13) ; v2(1564.31,3852.09) 1564.31,3864.68 1579.21,3879.58 v3(1578.95,3879.83)
  Inner Layer 5 w8: v3(1833,3849.4) 1832.86,3849.5 1833.65,3850.59 1848.68,3850.59 v2(1848.68,3850.36)
  Bottom w4: v2(1848.68,3850.36) C3102.1@1852.65,3850.59 1852.65,3850.36 v2(1848.68,3850.36)
  Bottom w6: R1035.2@1550.31,3798.09 R1035.2@1551.31,3798.09 ; v2(1564.31,3852.09) 1551.31,3839.09 R1035.2@1551.31,3798.09 ; v2(1586.28,2941.13) 1581.31,2946.09 1581.31,3173.73 1565.95,3189.09 1565.95,3452.14 1566.31,3452.5 1566.31,3607.35 1551.31,3622.35 R1035.2@1551.31,3798.09
VTCXO_1_PMU: R3709.1 TP3718.1 U2001.T16 | length 4054.3
  Top w4: R3709.1@2279.31,4488.09 2279.81,4488.59 v1(2280.31,4489.09)
  Top w6: TP3718.1@2252.31,4489.09 2279.31,4489.09 R3709.1@2279.81,4488.59
  Inner Layer 2 w4: v3(807.31,3020.09) 809.94,3022.72 v4(836.84,3022.72)
  Inner Layer 2 w6: v3(1043.59,2835.42) 1055.26,2847.09 1176.83,2847.09 1214.31,2884.58 1214.31,2903.09 1208.31,2909.09 v3(1198.31,2909.09) ; v1(2280.31,4489.09) 2300.91,4468.49 v3(2300.91,4404.1) ; v3(2289.31,3108.09) 2289.31,3097.09 2276.31,3084.09 2276.31,2984.09 2348.95,2911.45 v3(2348.95,2892.49)
  Inner Layer 4 w6: v3(807.31,3020.09) 799.31,3012.09 799.31,2966.52 843.75,2922.09 1185.31,2922.09 v3(1198.31,2909.09) ; v3(1043.59,2835.42) 1043.59,2829.06 1161.35,2711.3 2038.27,2711.3 2184.65,2857.67 2314.14,2857.67 v3(2348.95,2892.49) ; v3(2289.31,3108.09) 2295.31,3114.09 2345.82,3114.09 2488.43,3256.7 2488.43,3557.04 2513.65,3582.26 2513.65,3975.91 2306.31,4183.25 2306.31,4398.7 v3(2300.91,4404.1)
VUSB33_PMU: R1030.2 U2001.P11 | length 1114.8
  Top w4: v1(1124.95,3541.83) 1130.95,3541.83 R1030.2@1130.95,3539.49 ; v4(868.34,3101.46) 868.95,3101.83 868.71,3101.83 v4(868.34,3101.46)
  Inner Layer 2 w10: 815.31,3091.09 820.84,3091.09 845.21,3115.46 865.58,3115.46 868.95,3112.09 ; v4(868.34,3101.46) 868.34,3111.48 868.95,3112.09 ; v4@868.95,3101.83 868.95,3112.09 ; v1(1124.95,3541.83) 1126.95,3539.83 1126.95,3525.07 v3(1130.95,3521.07)
  Inner Layer 2 w12: 815.31,3091.09 814.31,3092.09 794.71,3092.09 777.71,3109.09 748.31,3109.09 732.31,3125.09 708.2,3125.09 702.2,3131.09 693.44,3131.09 628.31,3196.22 628.31,3225.33 597.31,3256.33 597.31,3325.29 682.11,3410.09 737.57,3410.09 753.57,3426.09 809.31,3426.09 810.31,3425.09 v3(827.31,3425.09)
  Inner Layer 5 w12: v3@826.31,3429.09 v3@827.31,3430.09 ; v3(827.31,3425.09) v3@827.31,3430.09 ; v3(1130.95,3521.07) 1127.92,3524.1 1082.91,3479.09 1014.31,3479.09 991.31,3456.09 960.69,3456.09 959.95,3456.83 854.05,3456.83 v3@827.31,3430.09
WATCHDOG: R2002.1 U1001.U4 | length 195.1
  Top w4: v1(1216.95,3562.49) 1218.3,3562.49 1218.3,3543.84 1218.95,3543.84 R2002.1@1218.95,3546.49
  Inner Layer 2 w3: 1228.31,3654.09 1229.31,3655.09 1230.55,3655.09 1241.45,3665.99 1241.45,3702.51 1234.95,3709.01 1234.95,3716.26 v4(1234.7,3716.51)
  Inner Layer 2 w4: v1(1216.95,3562.49) 1211.95,3567.49 1211.95,3637.73 1228.31,3654.09
WB_ANT: C5016.2 L5005.1 U5001.31 | length 52.1
  Top w5: L5005.1@1082.08,4500.11 L5005.1@1082.95,4499.24
  Top w10: U5001.31@1079.95,4471.17 1079.95,4497.98 L5005.1@1082.08,4500.11 C5016.2@1082.08,4521.11
WB_AVDD18: C5002.2 C5005.2 SH5002.1 U5001.29 | length 108.4
  Top w4: v1(1138.41,4425.15) 1138.41,4428.02 1139.45,4428.02 C5005.2@1139.45,4424.99
  Top w10: U5001.29@1105.15,4430.23 1130.72,4430.22 1135.96,4424.99 C5005.2@1139.45,4424.99
  Top w12: C5002.2@1139.45,4403.99 C5005.2@1139.45,4424.99
  Inner Layer 2 w12: v1(1138.31,4469.09) 1138.41,4468.99 v1(1138.41,4425.15)
WB_CTRL0: U1001.F29 U5001.23 | length 294.5
  Top w4: v1(1103.71,4335.74) U5001.23@1105.15,4335.74 ; U1001.F29@1061.19,4110.49 v4(1061.47,4110.21) U1001.F29@1061.19,4110.49
  Inner Layer 2 w4: v3(1046.31,4105.09) 1051.43,4110.21 v4(1061.47,4110.21) ; v3(1086.36,4335.09) 1086.31,4334.91 1103.71,4334.91 v1(1103.71,4335.74)
  Inner Layer 4 w4: v3(1046.31,4105.09) 1062.68,4105.09 1071.31,4113.72 1071.31,4319.09 1086.84,4334.62 v3(1086.36,4335.09)
WB_CTRL1: U1001.G29 U5001.24 | length 353.1
  Top w4: U5001.24@1105.15,4351.49 1105.39,4351.74 v1(1105.7,4351.74)
  Inner Layer 2 w4: v3(1060.31,4089.09) 1060.31,4093.3 v4(1077.22,4110.21) ; v3(1089.54,4356.9) 1088.79,4356.73 1088.31,4356.73 1088.31,4357.09 1089.83,4357.09 1095.18,4351.74 v1(1105.7,4351.74)
  Inner Layer 4 w4: v3(1060.31,4089.09) 1061.56,4089.09 1061.56,4092.5 1079.31,4110.25 1079.31,4306.09 1105.31,4332.09 1105.31,4348.67 1093.02,4360.96 1089.25,4357.19 1088.79,4356.73 v3(1089.54,4356.9)
WB_CTRL2: U1001.G28 U5001.25 | length 416.3
  Top w4: v4(1073.06,4070.9) 1075.08,4072.1 1075.08,4092.32 U1001.G28@1077.22,4094.47 ; U5001.25@1105.15,4367.24 v1(1111.95,4367.23)
  Inner Layer 2 w4: v4(1073.06,4070.9) 1103.31,4070.9 v3(1103.31,4071.09) ; v1(1111.95,4367.23) 1112.08,4367.11 1126.19,4381.21 v3(1126.31,4381.09)
  Inner Layer 4 w4: v3(1103.31,4071.09) 1104.93,4072.47 1116.62,4084.16 1116.62,4098.09 1103.31,4111.39 1103.31,4295.36 1129.31,4321.36 1129.31,4378.09 v3(1126.31,4381.09)
WB_CTRL3: U1001.H29 U5001.26 | length 372.3
  Top w4: U5001.26@1105.15,4382.98 1107.31,4382.98 v1(1107.31,4383.09)
  Inner Layer 2 w4: v3(1081.31,4087.09) 1081.31,4098.55 v4(1092.97,4110.21) ; v3(1086.32,4378.81) 1087.31,4378.99 1087.31,4380.09 1104.31,4380.09 v1(1107.31,4383.09)
  Inner Layer 4 w4: v3(1081.31,4087.09) 1081.31,4099.09 1087.31,4105.09 1087.31,4302.33 1113.31,4328.33 1113.31,4354.77 1088.21,4379.87 1087.34,4378.99 v3(1086.32,4378.81)
WB_CTRL4: U1001.H28 U5001.27 | length 485.7
  Top w4: U1001.H28@1092.97,4094.47 1092.97,4072.44 1106.31,4059.09 1105.31,4057.09 v4(1105.31,4054.09) ; U5001.27@1105.15,4398.73 1112.24,4398.73 1112.24,4399.17 v1(1115.77,4399.17)
  Inner Layer 2 w4: v4(1105.31,4054.09) 1105.31,4039.09 v3(1107.31,4038.09) ; v1(1115.77,4399.17) 1128.23,4399.17 1128.31,4399.09 1128.31,4401.09 v3(1130.31,4403.09)
  Inner Layer 4 w4: v3(1107.31,4038.09) 1107.31,4052.09 1123.62,4068.39 1123.62,4102.09 1111.31,4114.39 1111.31,4291.2 1141.31,4321.2 1141.31,4392.09 v3(1130.31,4403.09)
WB_CTRL5: U1001.J29 U5001.28 | length 375.5
  Top w4: U5001.28@1105.15,4414.48 1105.75,4415.09 v1(1106.31,4415.09)
  Inner Layer 2 w4: v3(1096.31,4399.09) 1097.31,4398.09 1106.31,4407.09 v1(1106.31,4415.09) ; v3(1102.31,4092.09) 1102.31,4103.81 v4(1108.72,4110.21)
  Inner Layer 4 w4: v3(1096.31,4399.09) 1107.31,4388.09 1107.31,4374.36 1121.31,4360.36 1121.31,4324.87 1095.31,4298.87 1095.31,4100.87 1102.62,4093.56 v3(1102.31,4092.09)
WB_RX_IN: U1001.J30 U5001.21 | length 206.1
  Top w3: U5001.21@1105.15,4304.24 1113.66,4304.24 1116.94,4300.97 1116.94,4296.24 1100.58,4279.88 1100.58,4227.12 1118.14,4209.56 1118.14,4135.38 1113.31,4130.56 U1001.J30@1108.72,4125.96
WB_RX_IP: U1001.K30 U5001.22 | length 227.8
  Top w3: U5001.22@1105.15,4319.99 1118.31,4319.99 1125.31,4312.99 1125.31,4296.12 1106.68,4277.49 1106.68,4230.39 1124.46,4212.61 U1001.K30@1124.46,4125.96
  Top w4: U5001.22@1104.42,4318.8 U5001.22@1104.45,4319.99 ; U5001.22@1104.45,4319.99 U5001.22@1105.15,4319.99 U5001.22@1104.45,4319.99
WB_RX_QN: U1001.H31 U5001.19 | length 151.9
  Top w3: U5001.19@1064.2,4279.05 1064.08,4278.93 1064.08,4268.11 1070.08,4262.11 1070.08,4218.61 1096.08,4192.61 1096.08,4144.82 U1001.H31@1092.97,4141.71
WB_RX_QP: U1001.J31 U5001.20 | length 152.5
  Top w3: U5001.20@1079.95,4279.05 1079.95,4270.11 1076.08,4266.24 1076.08,4221.11 1102.08,4195.11 1102.08,4148.34 U1001.J31@1108.72,4141.71
WB_TX_IN: U1001.G30 U5001.17 | length 171.5
  Top w3: U5001.17@1032.7,4279.05 1032.7,4268.11 1037.93,4262.88 1037.93,4243.26 1049.95,4231.24 1049.95,4211.11 1068.08,4192.98 1068.08,4162.36 1077.22,4153.22 U1001.G30@1077.22,4125.96
WB_TX_IP: U1001.H30 U5001.18 | length 187.7
  Top w3: U5001.18@1048.45,4279.05 1048.45,4267.25 1044.13,4262.92 1044.13,4245.84 1055.95,4234.01 1055.95,4213.78 1074.08,4195.65 1074.08,4165.49 1083.31,4156.26 1083.31,4135.62 U1001.H30@1092.97,4125.96 1084.08,4134.84
WB_TX_QN: U1001.F31 U5001.15 | length 162.3
  Top w3: U5001.15@1001.21,4279.05 1003.08,4277.17 1003.08,4266.99 1005.03,4265.04 1005.03,4244.67 1029.08,4220.62 1029.08,4191.11 1056.08,4164.11 1056.08,4147.1 U1001.F31@1061.47,4141.71
WB_TX_QP: U1001.F30 U5001.16 | length 188.3
  Top w3: U5001.16@1014.08,4276.17 U5001.16@1016.96,4279.05 1016.96,4268.81 1011.19,4263.05 1011.19,4247 1035.08,4223.11 1035.08,4193.59 1062.08,4166.59 1062.08,4158.51 1071.08,4149.51 1071.08,4135.57 U1001.F30@1061.47,4125.96
XMODE: R3107.1 U3101.L2 | length 121.7
  Top w4: R3107.1@1776.65,4053.59 1778.65,4051.59 R3107.1@1778.65,4050.59 1793.29,4035.95 1831.49,4035.95 1836.85,4030.59 1837.83,4030.59 1843.25,4025.17 1847.02,4025.17 1858.83,4013.35 1858.83,3997.9 U3101.L2@1863.66,3993.08
XTAL1: C3109.1 U3101.K2 U3102.4 | length 192.1
  Top w4: U3102.4@1741.38,4091.55 1741.38,4085.16 1761.42,4065.11 1811.05,4065.11 1815.95,4060.22 1815.95,4058.3 C3109.1@1823.65,4050.59 1823.65,4051.37 1824.43,4051.37 1831.85,4043.95 1836.29,4043.95 1836.65,4043.59 1836.65,4042.1 1840.17,4038.59 1841.66,4038.59 1844.37,4035.88 1847.62,4035.88 1867.35,4016.15 1867.35,4005.14 U3101.K2@1879.41,3993.08
XTAL2: C3108.2 U3101.K1 U3102.1 | length 180.3
  Top w4: U3102.1@1831.93,4149.63 1831.93,4140.23 1831.93,4128.75 1816.09,4112.91 1816.09,4072.83 1822.96,4065.95 1833.29,4065.95 C3108.2@1848.65,4050.59 1856.36,4042.88 1856.36,4039.45 1875.35,4020.46 1875.35,4014.55 1880.24,4009.66 U3101.K1@1879.41,4008.83
pads on no net: CON2101.6 CON2101.7 CON6001.6 CON6001.7 CON6102.6 CON6102.9 CON6102.12 CON6102.13 CON6102.14 CON6201.16 CON6201.19 CON6202.9 CON6202.10 CON6202.11 CON6202.14 CON6202.16 CON6202.21 CON6202.23 CON6202.26 CON6202.31 CON6202.32 CON6202.33 CON6202.34 CON6401.4 CON6501.4 CON6501.8 CON6502.4 CON6502.8 CON6503.3 CON6503.6 CON6503.7 CON6504.3 CON6504.6 CON6504.7 CON6505.3 CON6505.6 CON6505.7 CON9001.9 CON9001.10 CON9001.11 CON9001.12 CON9001.13 CON9001.14 CON9001.15 CON9001.16 CON9001.17 CON9001.18 CON9001.20 CON9001.22 CON9001.24 CON9001.25 CON9001.26 CON9001.28 CON9001.29 CON9001.30 CON9001.31 CON9001.32 CON9001.33 CON9001.34 CON9001.35 CON9001.36 CON9001.37 CON9001.39 FM9101.1 FM9102.1 FM9103.1 FM9104.1 FM9105.1 R3618.2 U1001.A1 U1001.A2 U1001.A30 U1001.A31 U1001.AC4 U1001.AD4 U1001.AD27 U1001.AD28 U1001.AD30 U1001.AE5 U1001.AE29 U1001.AE30 U1001.AE31 U1001.AF2 U1001.AF5 U1001.AF20 U1001.AF22 U1001.AF28 U1001.AG3 U1001.AG4 U1001.AG5 U1001.AG21 U1001.AG23 U1001.AG24 U1001.AG27 U1001.AG30 U1001.AH4 U1001.AH5 U1001.AH14 U1001.AH27 U1001.AJ14 U1001.AJ23 U1001.AK1 U1001.AK22 U1001.AK26 U1001.AK27 U1001.AL1 U1001.AL2 U1001.AL14 U1001.AL15 U1001.AL21 U1001.AL30 U1001.AL31 U1001.B1 U1001.B31 U1001.K28 U1001.L27 U1001.L28 U1001.L29 U1001.M27 U1001.M28 U1001.M30 U1001.M31 U1001.U28 U1001.U29 U1001.V28 U1001.V29 U1001.Y28 U2001.D2 U2001.J5 U2001.M9 U2001.R4 U2001.T1 U2401.9 U3101.A5 U3101.A14 U3101.A15 U3101.B5 U3101.B7 U3101.B8 U3101.F1 U3101.F3 U3101.H12 U3101.J14 U3101.K14 U3101.M9 U3101.M10 U3101.M12 U3102.2 U3102.5 U3203.9 U3203.10 U3203.11 U3203.16 U3203.17 U3203.19 U3203.26 U3203.41 U3307.19 U3307.24 U3307.25 U3402.8 U3402.14 U3701.A2 U3701.A4 U3701.A5 U3701.A9 U3701.A10 U3701.B1 U3701.B4 U3701.B5 U3701.C1 U3701.D1 U3701.E1 U3701.E2 U3701.F1 U3701.F2 U3701.G10 U3701.H9 U3701.J2 U3701.J6 U3701.J7 U3701.K6 U3701.K7 U3701.K10 U4102.A1 U4102.A2 U4102.A13 U4102.A14 U4102.AA1 U4102.AA14 U4102.AB1 U4102.AB2 U4102.AB13 U4102.AB14 U4102.B1 U4102.B14 U4102.D2 U4102.D3 U4102.D4 U4102.D5 U4102.D6 U4102.P10 U5001.3 U5001.30 U5001.32 U5001.35 U6301.A3 U6302.9 U6302.10 U6302.11 U6302.12 U6302.17 U6303.1 U6303.4 U6303.8 U6303.10 U6303.11
copper on no net: | length 43
  Bottom w20: 502.3,29.09 545.3,29.09

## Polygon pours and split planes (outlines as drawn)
VCORE_PMU on Inner Layer 4 "Inner Layer 4-VCORE_PMU" (solid, remove dead copper, pour order 0): 1136.08,3501.48 1129.08,3508.48 1129.08,3858.48 1138.08,3867.48 1239.08,3867.48 1247.08,3859.48 1247.08,3761.1 1343.95,3664.23 1343.95,3511.48 1333.95,3501.48
DVDD_LTE on Inner Layer 4 "Inner Layer 4-DVDD_LTE" (solid, remove dead copper, pour order 2): 1253.08,3763.1 1353.95,3662.23 1353.95,3511.48 1363.95,3501.48 1477.95,3501.48 1486.95,3510.48 1486.95,3637.23 1315.74,3808.44 1315.82,4044.36 1303.08,4057.1 1265.08,4057.1 1253.08,4045.1
D_GND on Inner Layer 4 "Inner Layer 4-D_GND" (solid, remove dead copper, pour order 16): -322.05,3874.49 1236.95,3874.49 1245.95,3883.49 1245.95,4045.49 1261.95,4061.49 1304.95,4061.49 1319.95,4046.49 1319.95,3810.49 1492.45,3637.99 1492.45,3509.49 1479.2,3496.24 1133.95,3496.24 1123.82,3506.37 1123.82,3874.49 -322.05,3874.49 -322.05,-229.51 2930.95,-229.51 2930.95,5378.49 -322.05,5378.49
D_GND on Inner Layer 5 "Inner Layer 5-D_GND" (solid, remove dead copper, pour order 4): -0.69,3943.49 464.28,3943.49 464.28,4242.37 835.07,4242.37 1030.95,4046.49 1077.95,4046.49 1114.95,4009.49 1268.95,4009.49 1306.95,3971.49 1306.95,3911.45 1322.31,3896.09 1322.31,3805.13 1405.31,3722.13 1405.31,3488.09 1175.31,3488.09 1149.95,3513.45 1149.95,3739.49 1124.45,3764.99 1095.95,3764.99 939.05,3608.09 464.23,3608.09 464.23,3943.09 -1.05,3943.09 -1.05,-190.51 2825.95,-190.51 2825.95,5276.49 -0.69,5276.49
VPROC_PMU on Inner Layer 5 "Inner Layer 5-VPROC_PMU" (solid, remove dead copper, pour order 6): 1182.92,3493.48 1153.08,3523.32 1153.08,3746.35 1109.08,3790.35 1109.08,3990.1 1118.08,3999.1 1263.08,3999.1 1295.08,3967.1 1295.08,3909.1 1315.08,3889.1 1315.08,3799.1 1397.08,3717.1 1397.08,3512.48 1396.95,3512.48 1396.95,3493.48
DVDD12_EMI on Inner Layer 5 "Inner Layer 5-DVDD12_EMI" (solid, remove dead copper, pour order 14): 470.93,3611.09 470.93,4236.31 828.88,4236.31 1030.08,4035.11 1078.08,4035.11 1103.08,4010.11 1103.08,3780.94 1022.08,3700.37 1022.08,3700.11 933.06,3611.09
D_GND on Bottom "Bottom-D_GND" (solid, remove dead copper, pour order 8): 2933.3,5380.09 -323.7,5380.09 -323.7,-230.91 2933.3,-230.91
D_GND on Inner Layer 3 "Inner Layer 3-D_GND" (solid, remove dead copper, pour order 10): 2933.3,5380.09 -323.7,5380.09 -323.7,-230.91 2933.3,-230.91
D_GND on Top "Top-D_GND" (solid, remove dead copper, pour order 12): 2937.3,5383.09 -319.7,5383.09 -319.7,-227.91 2937.3,-227.91
D_GND on Inner Layer 2 "Inner Layer 2-D_GND" (solid, remove dead copper, pour order 18): 2933.3,5380.09 -323.7,5380.09 -323.7,-230.91 2933.3,-230.91

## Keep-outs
Keep-Out Layer:
  pour cut-out: 28.3,376.09 1726.3,376.09 1726.3,-30.91 28.3,-30.91 28.3,376.09
  pour cut-out: 40.31,4654.09 318.31,4654.09 188.81,4524.59 40.31,4524.59 40.31,4654.09
  pour cut-out: 388.3,588.09 991.3,588.09 991.3,376.09 388.3,376.09 388.3,588.09
  pour cut-out: 1112.3,596.09 1633.3,596.09 1633.3,376.09 1112.3,376.09 1112.3,596.09
  pour cut-out: 2558.31,4205.09 2652.31,4205.09 2652.31,3499.09 2558.31,3499.09 2558.31,4205.09
  pour cut-out: 2111.3,-25.91 2644.3,-25.91 2644.3,336.09 2111.3,336.09 2111.3,-25.91
  pour cut-out: 2197.3,4789.09 2177.3,4809.09 2177.3,5095.09 2634.3,5095.09 2634.3,4568.09 2303.3,4568.09 2224.3,4647.09 2224.3,4789.09 2197.3,4789.09
  pour cut-out: 2110.31,166.09 2110.31,337.09 2646.31,337.09 2646.31,-25.91 2034.31,-25.91 2034.31,166.09 2110.31,166.09
  pour cut-out: -18.69,4650.59 -18.69,5101.09 610.31,5101.09 610.31,4842.09 418.81,4650.59 -18.69,4650.59
  lines w10: 55.11,4649.21 ccw(c51.18,4668.5) 70.87,4668.5 70.87,4803.15 ccw(c51.18,4803.15) 51.18,4822.84 47.24,4822.84 cw(c47.24,4842.52) 27.56,4842.52 27.56,4901.58 cw(c86.61,4901.58) 86.61,4960.63 125.98,4960.63 ccw(c125.98,5039.37) 204.72,5039.37 cw(c263.78,5039.37) 263.78,5098.43 918.96,5098.43 ccw(c918.96,5177.17) 964.12,5112.67 1019.03,5151.12 cw(c1064.2,5086.62) 1064.2,5165.36 1408.24,5165.36 cw(c1408.24,5086.62) 1453.41,5151.12 1508.32,5112.67 ccw(c1553.48,5177.17) 1553.48,5098.43 1905.51,5098.43 1911.42,5092.52 2405.64,5092.52 cw(c2405.64,5033.47) 2464.64,5036.04 ; 55.13,4649.21 ccw(c59.06,4629.92) 39.37,4629.92 39.37,3661.42 ccw(c59.06,3661.42) 49.21,3644.37 cw(c39.37,3627.32) 59.06,3627.32 59.06,3093.52 ccw(c78.74,3093.52) 78.74,3073.83 149.61,3073.83 cw(c149.61,3058.08) 165.35,3058.08 165.35,2991.15 cw(c149.61,2991.15) 149.61,2975.41 47.24,2975.41 ccw(c47.25,2955.72) 27.56,2955.72 27.56,2677.17 ccw(c47.24,2677.17) 47.24,2657.48 55.12,2657.48 cw(c55.12,2578.74) 55.12,2500 47.24,2500 ccw(c47.24,2480.32) 27.56,2480.32 27.56,2263.78 ccw(c47.24,2263.78) 43.32,2244.49 cw(c39.37,2225.21) 59.06,2225.21 59.06,1593.69 cw(c39.37,1593.69) 43.29,1574.4 ccw(c47.24,1555.12) 27.56,1555.12 27.56,1493.11 cw(c7.87,1493.11) 16.19,1475.27 11.37,1473.02 ccw(c19.69,1455.18) 0,1455.18 0,840.35 ccw(c19.68,840.35) 11.37,822.51 16.19,820.26 cw(c7.87,802.42) 27.56,802.42 27.56,551.18 ccw(c47.24,551.18) 47.24,531.5 66.93,531.5 cw(c66.93,452.76) 66.93,374.02 47.24,374.02 ccw(c47.24,354.33) 27.56,354.33 27.56,157.48 ccw(c185.04,157.48) 185.04,0 2405.51,0 ccw(c2405.51,59.06) 2464.57,59.06 2464.57,98.43 cw(c2543.31,98.43) 2543.31,177.17 2582.68,177.17 ccw(c2582.68,236.22) 2641.73,236.22 2641.73,612.05 ccw(c2622.05,612.05) 2627.97,630.83 cw(c2633.86,649.61) 2614.17,649.61 2614.17,787.4 cw(c2633.87,787.4) 2627.95,806.18 ccw(c2622.05,824.96) 2641.73,824.96 2641.73,925.2 2586.61,925.2 2586.61,1122.05 1992.13,1122.05 ccw(c1992.13,1102.36) 1972.44,1102.36 1972.44,905.51 cw(c1952.76,905.51) 1952.76,885.83 1755.91,885.83 cw(c1755.91,905.51) 1736.22,905.51 1736.22,1102.36 ccw(c1716.54,1102.36) 1716.54,1122.05 796.66,1122.05 cw(c797.02,1141.75) 777.31,1141.68 777.31,2240.99 ccw(c766.61,2240.13) 765.75,2250.83 cw(c766.45,2259.97) 757.31,2260.67 757.31,2555.95 cw(c766.45,2556.65) 765.75,2565.79 ccw(c765.75,2575.63) 775.59,2575.63 775.59,2594.61 cw(c795.28,2594.61) 795.28,2614.3 2586.61,2614.3 2586.61,3275.59 2641.73,3275.59 2641.73,3366.14 2614.17,3366.14 cw(c2614.17,3444.88) 2614.17,3523.62 2622.05,3523.62 ccw(c2622.05,3543.31) 2641.73,3543.31 2641.73,3661.42 ccw(c2622.05,3661.42) 2625.97,3680.71 ; 236.22,3024.62 283.46,3024.62 ; 417.32,3024.62 464.57,3024.62 ; 2464.64,5035.94 ccw(c2543.31,5039.37) 2543.31,4960.63 2574.8,4960.63 cw(c2574.8,4901.58) 2633.86,4901.58 2633.86,4533.47 cw(c2614.17,4533.47) 2614.17,4513.78 2472.44,4513.78 ccw(c2472.44,4501.97) 2460.63,4501.97 2460.63,4218.51 ccw(c2472.44,4218.51) 2472.44,4206.69 2622.05,4206.69 cw(c2622.05,4187.01) 2641.73,4187.01 2641.73,3874.02 cw(c2622.05,3874.02) 2625.97,3854.73 ; 2626,3680.7 cw(c2629.92,3699.99) 2610.24,3699.99 2610.24,3835.44 cw(c2629.92,3835.44) 2626,3854.73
